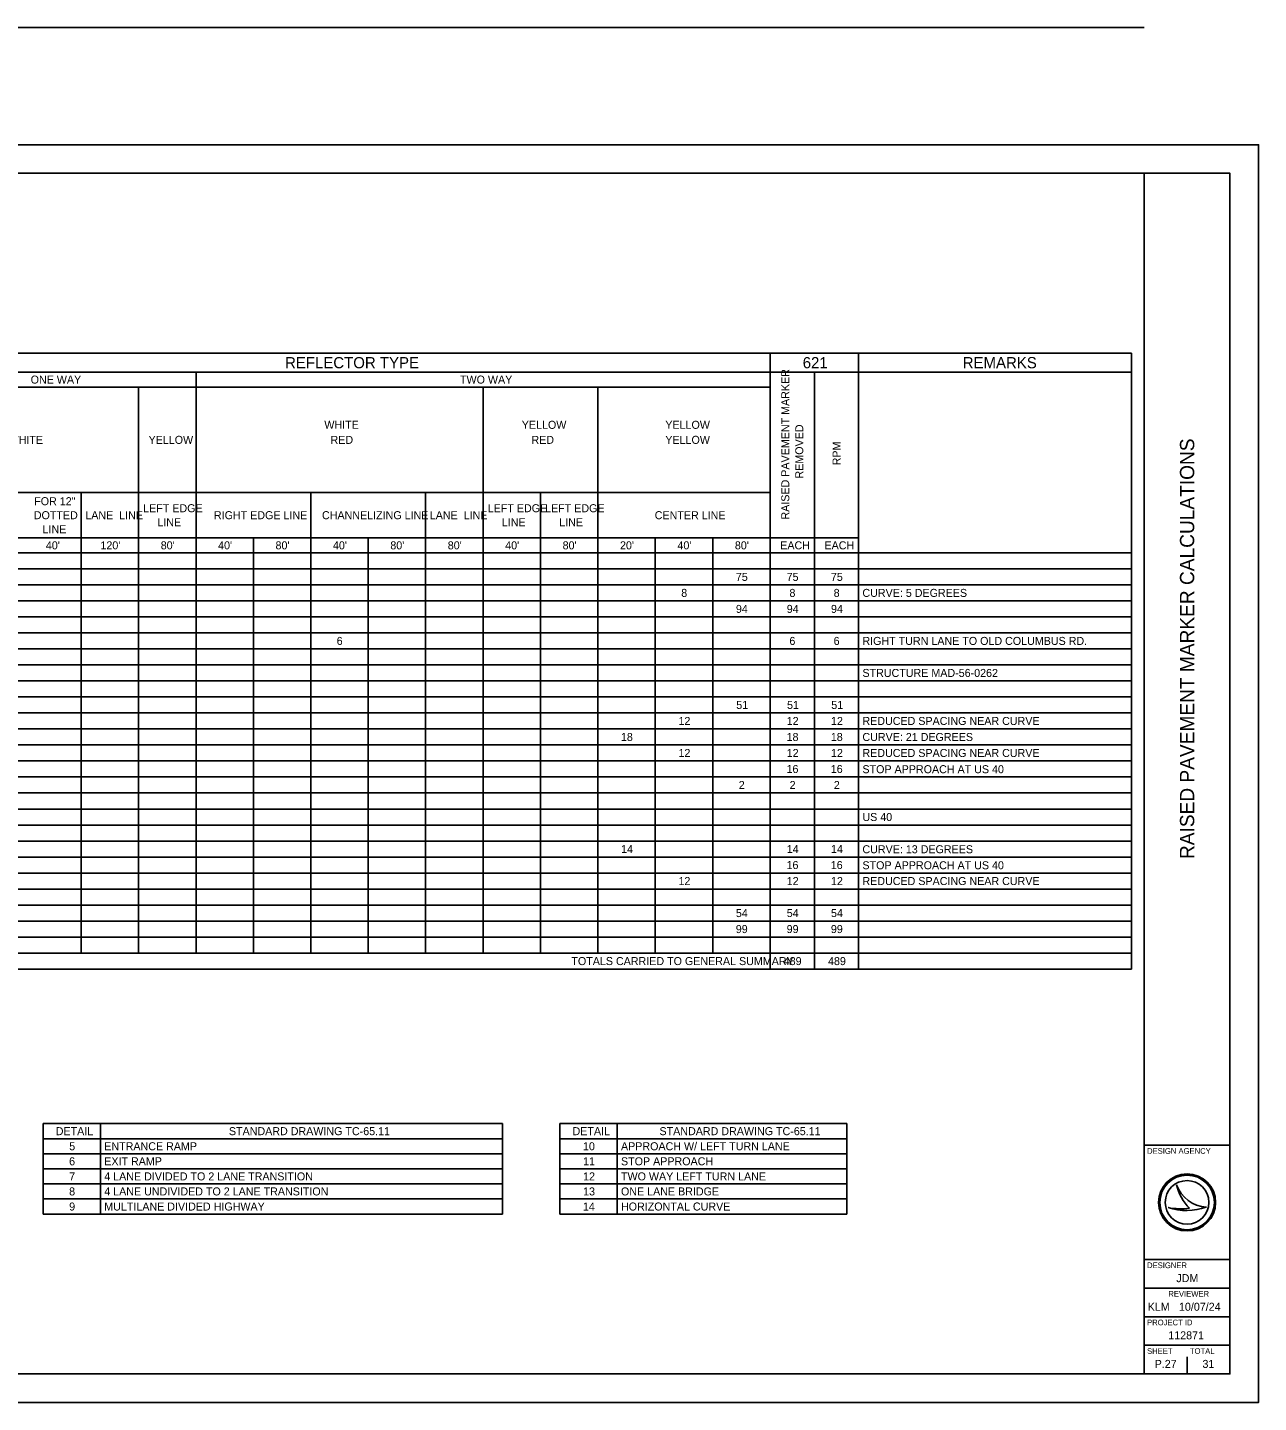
# Model space of a CAD drawing. Extents: x -2.5 to 34, y 0 to 24.1.
# Drawn here: x 12.46 to 34, y 0 to 24.05 of the extents above; entities that cross this region are included whole.
import ezdxf

# ---------------------------------------------------------------- set-up
doc = ezdxf.new("R2010")
doc.units = 0
for name, color, linetype in [('SH_Border', 7, 'Continuous'), ('SH_Cut_Line', 7, 'Continuous'), ('SH_Data', 7, 'Continuous'), ('SH_Text', 7, 'Continuous')]:
    doc.layers.add(name, color=color, linetype=linetype)

msp = doc.modelspace()

# ---------------------------------------------------------------- linework, layer by layer
at = {"layer": 'SH_Border'}
for p, q in [((32, 0.5), (32, 21.5)), ((32, 4.5), (33.5, 4.5)), ((32, 2.5), (33.5, 2.5)), ((32, 2), (33.5, 2)), ((32, 1.5), (33.5, 1.5)), ((32, 1), (33.5, 1))]:
    msp.add_line(p, q, dxfattribs=at)
msp.add_lwpolyline([(1.5, 21.5), (33.5, 21.5), (33.5, 0.5), (1.5, 0.5)], close=True, dxfattribs=at)
at = {"layer": 'SH_Cut_Line'}
msp.add_lwpolyline([(0, 0), (34, 0), (34, 22), (0, 22)], close=True, dxfattribs=at)
at = {"layer": 'SH_Data'}
for p, q in [((32.567, 3.81), (32.567, 3.81)), ((32.417, 3.41), (32.417, 3.41)), ((32.75, 3.5), (32.75, 3.5)), ((33.087, 3.419), (33.087, 3.419)), ((32.75, 0.5), (32.75, 0.8)), ((32.375, 0.675), (32.375, 0.675))]:
    msp.add_line(p, q, dxfattribs=at)
for radius in [0.5, 0.477, 0.477, 0.382]:
    msp.add_circle((32.75, 3.5), radius, dxfattribs=at)
for centre, radius, start, end in [((33.116, 3.998), 0.58, 198.9257, 198.9319), ((33.347, 3.97), 0.796, 191.6379, 191.6421), ((33.116, 3.998), 0.58, 198.9319, 267.1657), ((33.347, 3.97), 0.796, 191.6421, 226.0947), ((32.739, 4.37), 1.013, 251.4576, 290.0832), ((32.648, 4.654), 1.266, 259.4964, 259.4995), ((32.739, 4.37), 1.013, 251.4527, 251.4576), ((32.648, 4.654), 1.266, 259.4995, 276.6672)]:
    msp.add_arc(centre, radius, start, end, dxfattribs=at)
at = {"layer": 'SH_Text'}
for p, q in [((1.5, 24.051), (32, 24.051)), ((1.721, 18.353), (31.779, 18.353)), ((25.455, 18.353), (25.455, 7.581)), ((27.003, 18.353), (27.003, 7.581)), ((31.779, 18.353), (31.779, 7.581)), ((1.721, 18.023), (31.779, 18.023)), ((15.408, 18.023), (15.408, 7.861)), ((26.229, 18.023), (26.229, 7.861)), ((10.384, 17.76), (25.455, 17.76)), ((14.403, 17.76), (14.403, 7.861)), ((20.431, 17.76), (20.431, 7.861)), ((22.441, 17.76), (22.441, 7.861)), ((10.384, 15.915), (25.455, 15.915)), ((13.398, 15.915), (13.398, 7.861)), ((17.417, 15.915), (17.417, 7.861)), ((19.426, 15.915), (19.426, 7.861)), ((21.436, 15.915), (21.436, 7.861)), ((10.384, 15.125), (27.003, 15.125)), ((16.412, 15.125), (16.412, 7.861)), ((18.422, 15.125), (18.422, 7.861)), ((23.445, 15.125), (23.445, 7.861)), ((24.45, 15.125), (24.45, 7.861)), ((1.721, 14.861), (31.779, 14.861)), ((1.721, 14.581), (31.779, 14.581)), ((1.721, 14.301), (31.779, 14.301)), ((1.721, 14.021), (31.779, 14.021)), ((1.721, 13.741), (31.779, 13.741)), ((1.721, 13.461), (31.779, 13.461)), ((1.721, 13.181), (31.779, 13.181)), ((1.721, 12.901), (31.779, 12.901)), ((1.721, 12.621), (31.779, 12.621)), ((1.721, 12.341), (31.779, 12.341)), ((1.721, 12.061), (31.779, 12.061)), ((1.721, 11.781), (31.779, 11.781)), ((1.721, 11.501), (31.779, 11.501)), ((1.721, 11.221), (31.779, 11.221)), ((1.721, 10.941), (31.779, 10.941)), ((1.721, 10.661), (31.779, 10.661)), ((1.721, 10.381), (31.779, 10.381)), ((1.721, 10.101), (31.779, 10.101)), ((1.721, 9.821), (31.779, 9.821)), ((1.721, 9.541), (31.779, 9.541)), ((1.721, 9.261), (31.779, 9.261)), ((1.721, 8.981), (31.779, 8.981)), ((1.721, 8.701), (31.779, 8.701)), ((1.721, 8.421), (31.779, 8.421)), ((1.721, 8.141), (31.779, 8.141)), ((1.721, 7.861), (31.779, 7.861)), ((26.229, 7.861), (26.229, 7.581)), ((1.721, 7.581), (31.779, 7.581)), ((12.731, 4.878), (20.769, 4.878)), ((12.731, 4.878), (12.731, 3.296)), ((13.736, 4.878), (13.736, 3.296)), ((20.769, 4.878), (20.769, 3.296)), ((21.774, 4.878), (26.797, 4.878)), ((21.774, 4.878), (21.774, 3.296)), ((22.778, 4.878), (22.778, 3.296)), ((26.797, 4.878), (26.797, 3.296)), ((12.731, 4.614), (20.769, 4.614)), ((21.774, 4.614), (26.797, 4.614)), ((12.731, 4.35), (20.769, 4.35)), ((21.774, 4.35), (26.797, 4.35)), ((12.731, 4.087), (20.769, 4.087)), ((21.774, 4.087), (26.797, 4.087)), ((12.731, 3.823), (20.769, 3.823)), ((21.774, 3.823), (26.797, 3.823)), ((12.731, 3.56), (20.769, 3.56)), ((21.774, 3.56), (26.797, 3.56)), ((12.731, 3.296), (20.769, 3.296)), ((21.774, 3.296), (26.797, 3.296))]:
    msp.add_line(p, q, dxfattribs=at)

# ---------------------------------------------------------------- texts
at = {"layer": 'SH_Data'}
msp.add_text('RAISED PAVEMENT MARKER CALCULATIONS', height=0.25, rotation=90, dxfattribs=at).set_placement((32.875, 9.506))
for s, height, p in [('DESIGN AGENCY', 0.1, (32.05, 4.35)), ('DESIGNER', 0.1, (32.05, 2.35)), ('JDM', 0.14, (32.562, 2.105)), ('REVIEWER', 0.1, (32.422, 1.85)), ('KLM', 0.14, (32.061, 1.605)), ('10/07/24', 0.14, (32.608, 1.605)), ('PROJECT ID', 0.1, (32.05, 1.35)), ('112871', 0.14, (32.421, 1.105)), ('SHEET', 0.1, (32.05, 0.85)), ('P.27', 0.14, (32.183, 0.605)), ('TOTAL', 0.1, (32.8, 0.85)), ('31', 0.14, (33.019, 0.605))]:
    msp.add_text(s, height=height, dxfattribs=at).set_placement(p)
at = {"layer": 'SH_Text'}
for s, height, p in [('REFLECTOR TYPE', 0.196, (16.965, 18.09)), ('621', 0.196, (26.024, 18.09)), ('REMARKS', 0.196, (28.824, 18.09)), ('ONE WAY', 0.14, (12.514, 17.822)), ('TWO WAY', 0.14, (20.027, 17.822)), ('WHITE', 0.14, (17.653, 17.031)), ('YELLOW', 0.14, (21.108, 17.031)), ('YELLOW', 0.14, (23.62, 17.031)), ('WHITE', 0.14, (12.127, 16.768)), ('YELLOW', 0.14, (14.577, 16.768)), ('RED', 0.14, (17.761, 16.768)), ('RED', 0.14, (21.277, 16.768)), ('YELLOW', 0.14, (23.62, 16.768)), ('FOR 12" ', 0.14, (12.576, 15.695)), ('LEFT EDGE  ', 0.14, (14.483, 15.572)), ('LEFT EDGE  ', 0.14, (20.512, 15.572)), ('LEFT EDGE  ', 0.14, (21.516, 15.572)), ('DOTTED ', 0.14, (12.569, 15.45)), ('LANE  LINE', 0.14, (13.47, 15.45)), ('LINE', 0.14, (14.731, 15.327)), ('RIGHT EDGE LINE', 0.14, (15.721, 15.45)), ('CHANNELIZING LINE', 0.14, (17.612, 15.45)), ('LANE  LINE', 0.14, (19.498, 15.45)), ('LINE', 0.14, (20.759, 15.327)), ('LINE', 0.14, (21.764, 15.327)), ('CENTER LINE', 0.14, (23.435, 15.45)), ('LINE', 0.14, (12.722, 15.205)), ("40'", 0.14, (12.78, 14.923)), ("120'", 0.14, (13.735, 14.923)), ("80'", 0.14, (14.79, 14.923)), ("40'", 0.14, (15.794, 14.923)), ("80'", 0.14, (16.799, 14.923)), ("40'", 0.14, (17.804, 14.923)), ("80'", 0.14, (18.808, 14.923)), ("80'", 0.14, (19.813, 14.923)), ("40'", 0.14, (20.818, 14.923)), ("80'", 0.14, (21.823, 14.923)), ("20'", 0.14, (22.827, 14.923)), ("40'", 0.14, (23.832, 14.923)), ("80'", 0.14, (24.837, 14.923)), ('EACH', 0.14, (25.631, 14.923)), ('EACH', 0.14, (26.405, 14.923)), ('75', 0.14, (24.854, 14.371)), ('75', 0.14, (25.743, 14.371)), ('75', 0.14, (26.517, 14.371)), ('8', 0.14, (23.898, 14.091)), ('8', 0.14, (25.792, 14.091)), ('8', 0.14, (26.566, 14.091)), ('CURVE: 5 DEGREES', 0.14, (27.069, 14.091)), ('94', 0.14, (24.855, 13.811)), ('94', 0.14, (25.745, 13.811)), ('94', 0.14, (26.519, 13.811)), ('6', 0.14, (17.869, 13.251)), ('6', 0.14, (25.791, 13.251)), ('6', 0.14, (26.565, 13.251)), ('RIGHT TURN LANE TO OLD COLUMBUS RD.', 0.14, (27.069, 13.251)), ('STRUCTURE MAD-56-0262', 0.14, (27.069, 12.691)), ('51', 0.14, (24.861, 12.131)), ('51', 0.14, (25.75, 12.131)), ('51', 0.14, (26.524, 12.131)), ('12', 0.14, (23.85, 11.851)), ('12', 0.14, (25.744, 11.851)), ('12', 0.14, (26.519, 11.851)), ('REDUCED SPACING NEAR CURVE', 0.14, (27.069, 11.851)), ('18', 0.14, (22.843, 11.571)), ('18', 0.14, (25.742, 11.571)), ('18', 0.14, (26.516, 11.571)), ('CURVE: 21 DEGREES', 0.14, (27.069, 11.571)), ('12', 0.14, (23.85, 11.291)), ('12', 0.14, (25.744, 11.291)), ('12', 0.14, (26.519, 11.291)), ('REDUCED SPACING NEAR CURVE', 0.14, (27.069, 11.291)), ('16', 0.14, (25.741, 11.011)), ('16', 0.14, (26.515, 11.011)), ('STOP APPROACH AT US 40', 0.14, (27.069, 11.007)), ('2', 0.14, (24.905, 10.731)), ('2', 0.14, (25.795, 10.731)), ('2', 0.14, (26.569, 10.731)), ('US 40', 0.14, (27.069, 10.171)), ('14', 0.14, (22.846, 9.611)), ('14', 0.14, (25.745, 9.611)), ('14', 0.14, (26.519, 9.611)), ('CURVE: 13 DEGREES', 0.14, (27.069, 9.607)), ('16', 0.14, (25.741, 9.331)), ('16', 0.14, (26.515, 9.331)), ('STOP APPROACH AT US 40', 0.14, (27.069, 9.327)), ('12', 0.14, (23.85, 9.051)), ('12', 0.14, (25.744, 9.051)), ('12', 0.14, (26.519, 9.051)), ('REDUCED SPACING NEAR CURVE', 0.14, (27.069, 9.051)), ('54', 0.14, (24.855, 8.491)), ('54', 0.14, (25.745, 8.491)), ('54', 0.14, (26.519, 8.491)), ('99', 0.14, (24.853, 8.211)), ('99', 0.14, (25.743, 8.211)), ('99', 0.14, (26.517, 8.211)), ('TOTALS CARRIED TO GENERAL SUMMARY', 0.14, (21.976, 7.651)), ('489', 0.14, (25.692, 7.651)), ('489', 0.14, (26.467, 7.651)), ('DETAIL', 0.14, (12.953, 4.676)), ('STANDARD DRAWING TC-65.11', 0.14, (15.983, 4.676)), ('DETAIL', 0.14, (21.996, 4.676)), ('STANDARD DRAWING TC-65.11', 0.14, (23.518, 4.676)), ('5', 0.14, (13.189, 4.412)), ('ENTRANCE RAMP', 0.14, (13.802, 4.412)), ('10', 0.14, (22.179, 4.412)), ('APPROACH W/ LEFT TURN LANE', 0.14, (22.844, 4.412)), ('6', 0.14, (13.187, 4.149)), ('EXIT RAMP', 0.14, (13.802, 4.149)), ('11', 0.14, (22.181, 4.149)), ('STOP APPROACH', 0.14, (22.844, 4.149)), ('7', 0.14, (13.188, 3.885)), ('4 LANE DIVIDED TO 2 LANE TRANSITION', 0.14, (13.802, 3.885)), ('12', 0.14, (22.181, 3.885)), ('TWO WAY LEFT TURN LANE', 0.14, (22.844, 3.885)), ('8', 0.14, (13.187, 3.622)), ('4 LANE UNDIVIDED TO 2 LANE TRANSITION', 0.14, (13.802, 3.622)), ('13', 0.14, (22.181, 3.622)), ('ONE LANE BRIDGE', 0.14, (22.844, 3.622)), ('9', 0.14, (13.188, 3.358)), ('MULTILANE DIVIDED HIGHWAY', 0.14, (13.802, 3.358)), ('14', 0.14, (22.178, 3.358)), ('HORIZONTAL CURVE', 0.14, (22.844, 3.358))]:
    msp.add_text(s, height=height, dxfattribs=at).set_placement(p)
for s, p in [('RAISED PAVEMENT MARKER ', (25.789, 15.444)), ('REMOVED', (26.034, 16.161)), ('RPM', (26.686, 16.392))]:
    msp.add_text(s, height=0.14, rotation=90, dxfattribs=at).set_placement(p)

doc.saveas('drawing.dxf')
